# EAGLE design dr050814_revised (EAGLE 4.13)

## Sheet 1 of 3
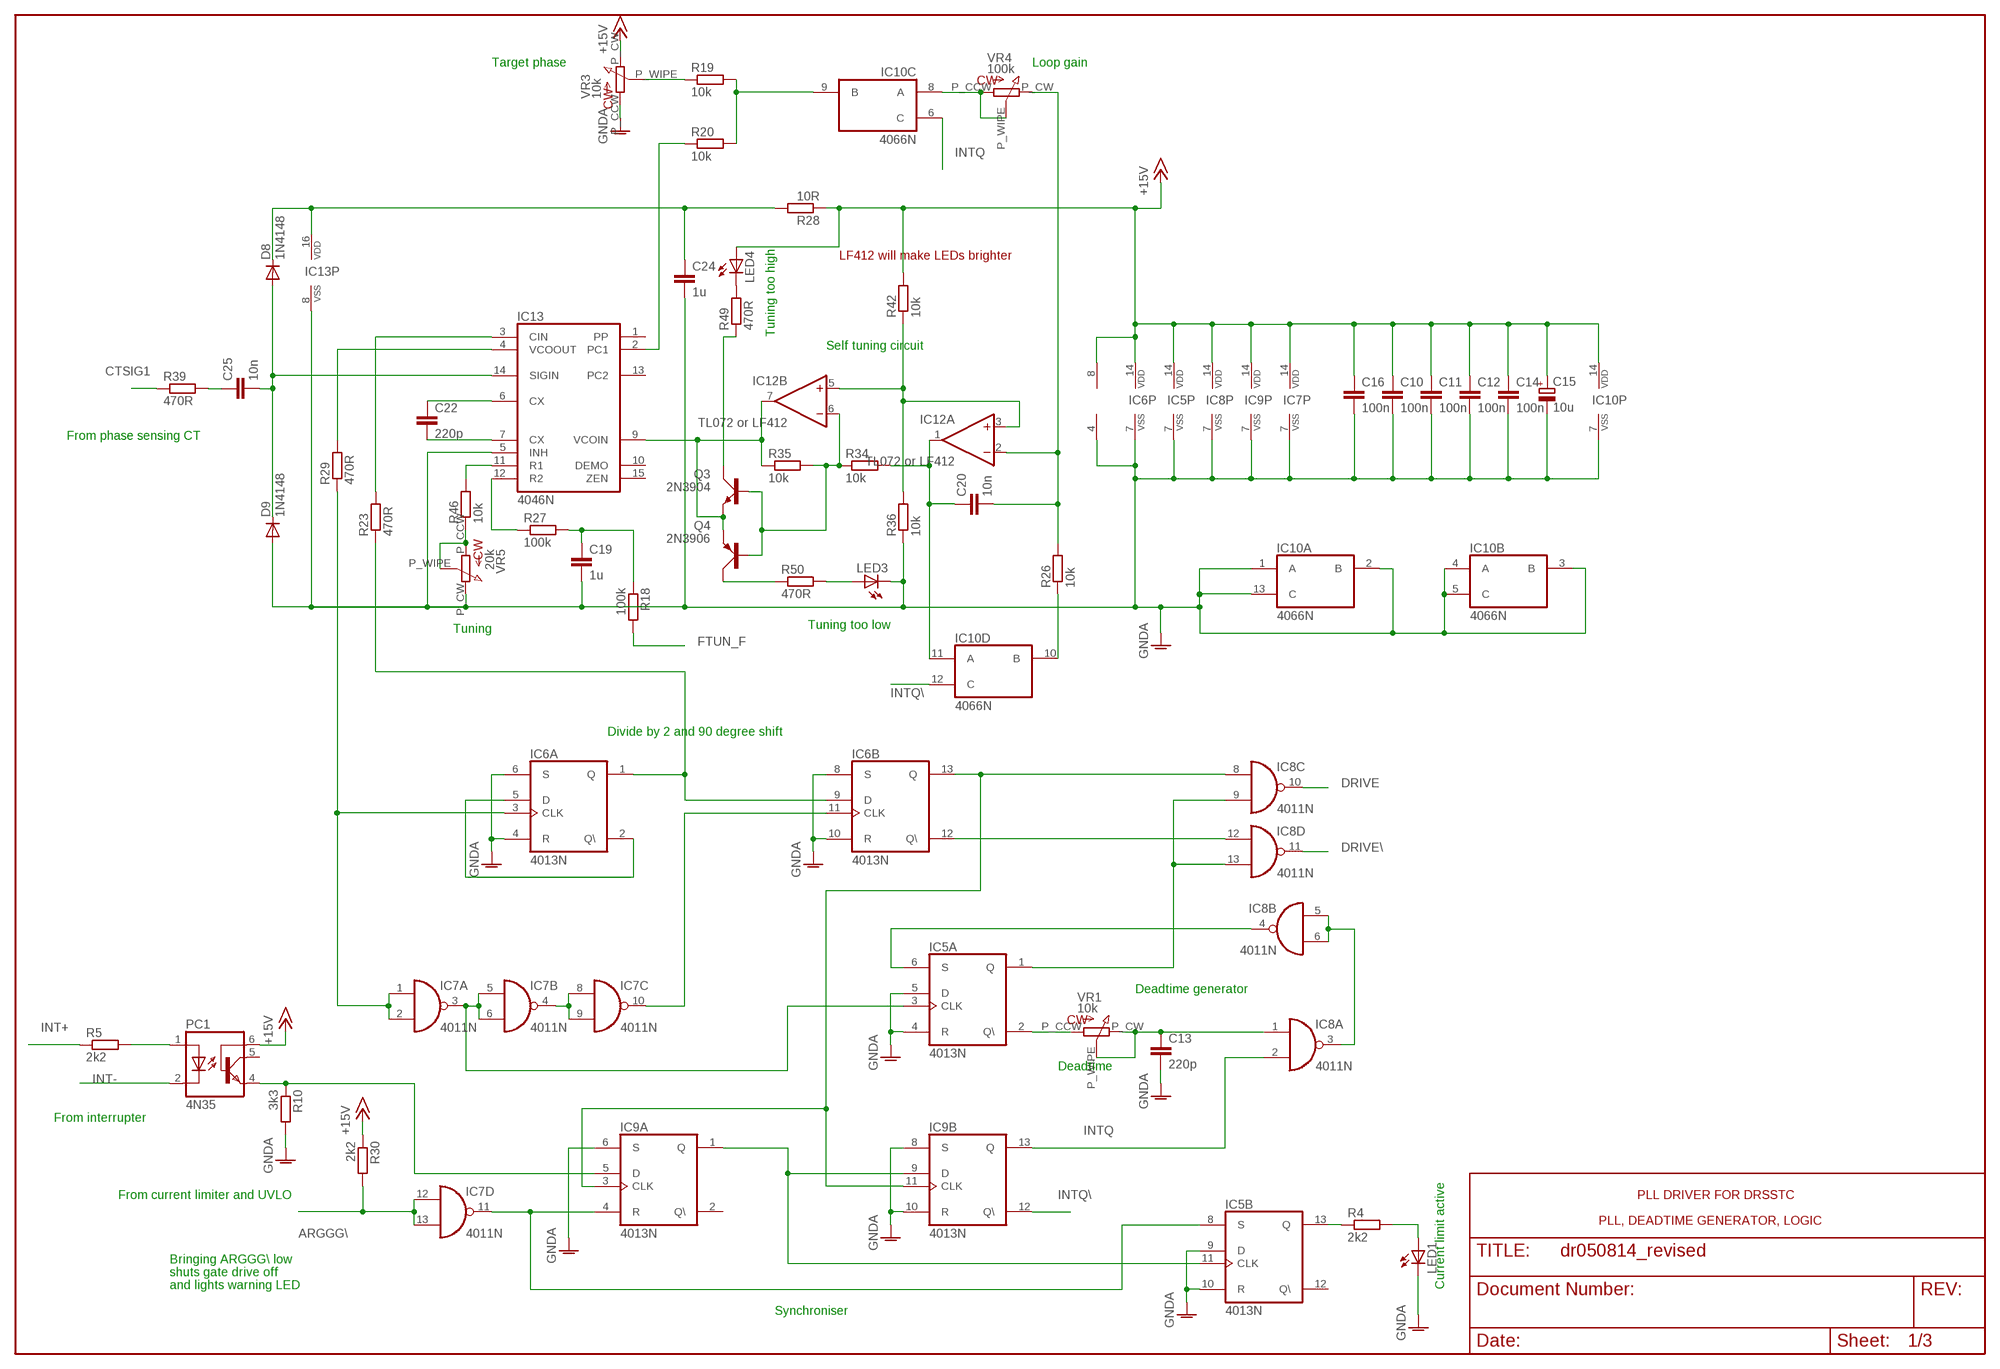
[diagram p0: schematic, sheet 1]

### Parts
C10  100n  C-EU050-025X075  [C050-025X075]
C11  100n  C-EU050-025X075  [C050-025X075]
C12  100n  C-EU050-025X075  [C050-025X075]
C13  220p  C-EU050-025X075  [C050-025X075]
C14  100n  C-EU050-025X075  [C050-025X075]
C15  10u  CPOL-EUTT6D6  [TT5D6]
C16  100n  C-EU050-025X075  [C050-025X075]
C19  1u  C-EU050-025X075  [C050-025X075]
C20  10n  C-EU050-025X075  [C050-025X075]
C22  220p  C-EU050-025X075  [C050-025X075]
C24  1u  C-EU050-025X075  [C050-025X075]
C25  10n  C-EU050-025X075  [C050-025X075]
D8  1N4148  [DO35-10]
D9  1N4148  [DO35-10]
IC5  4013N  [DIL14]
IC6  4013N  [DIL14]
IC7  4011N  [DIL14]
IC8  4011N  [DIL14]
IC9  4013N  [DIL14]
IC10  4066N  [DIL14]
IC12  TL072 or LF412  2AMP_P8+4N  [DIL08]
IC13  4046N  [DIL16]
LED1  LED5MM  [LED5MM]
LED3  LED5MM  [LED5MM]
LED4  LED5MM  [LED5MM]
PC1  4N35  [DIL06]
Q3  2N3904  [TO92D]
Q4  2N3906  [TO92D]
R4  2k2  R-EU_0207/10  [0207/10]
R5  2k2  R-EU_0207/10  [0207/10]
R10  3k3  R-EU_0207/10  [0207/10]
R18  100k  R-EU_0207/10  [0207/10]
R19  10k  R-EU_0207/10  [0207/10]
R20  10k  R-EU_0207/10  [0207/10]
R23  470R  R-EU_0207/10  [0207/10]
R26  10k  R-EU_0207/10  [0207/10]
R27  100k  R-EU_0207/10  [0207/10]
R28  10R  R-EU_0207/10  [0207/10]
R29  470R  R-EU_0207/10  [0207/10]
R30  2k2  R-EU_0207/10  [0207/10]
R34  10k  R-EU_0207/10  [0207/10]
R35  10k  R-EU_0207/10  [0207/10]
R36  10k  R-EU_0207/10  [0207/10]
R39  470R  R-EU_0207/10  [0207/10]
R42  10k  R-EU_0207/10  [0207/10]
R46  10k  R-EU_0207/10  [0207/10]
R49  470R  R-EU_0207/10  [0207/10]
R50  470R  R-EU_0207/10  [0207/10]
VR1  10k  POT  [SPECTROL149]
VR3  10k  POT  [SPECTROL149]
VR4  100k  POT  [SPECTROL149]
VR5  20k  POT  [SPECTROL149]

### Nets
+15V: C10.1 C11.1 C12.1 C14.1 C15.+ C16.1 IC5.14(P:VDD) IC6.14(P:VDD) IC7.14(P:VDD) IC8.14(P:VDD) IC9.14(P:VDD) IC10.14(P:VDD) IC12.8(P:V+) LED4.A PC1.6(BAS) R28.1 R30.1 R42.2 VR3.P_CW(CW) ; also sheet 2,3
ARGGG\: IC7.12(D:I0) IC7.13(D:I1) R30.2 ; also sheet 2
CTSIG1: R39.1 ; also sheet 3
DRIVE: IC8.10(C:O) ; also sheet 3
DRIVE\: IC8.11(D:O) ; also sheet 3
FTUN_F: R18.2 ; also sheet 3
GNDA: C10.2 C11.2 C12.2 C13.2 C14.2 C15.- C16.2 C19.2 C24.2 D9.A IC5.4(A:R) IC5.5(A:D) IC5.7(P:VSS) IC5.9(B:D) IC5.10(B:R) IC6.4(A:R) IC6.6(A:S) IC6.7(P:VSS) IC6.8(B:S) IC6.10(B:R) IC7.7(P:VSS) IC8.7(P:VSS) IC9.6(A:S) IC9.7(P:VSS) IC9.8(B:S) IC9.10(B:R) IC10.1(A:A) IC10.2(A:B) IC10.3(B:B) IC10.4(B:A) IC10.5(B:C) IC10.7(P:VSS) IC10.13(A:C) IC12.4(P:V-) IC13.5(INH) IC13.8(VSS) LED1.K(C) LED3.K(C) R10.2 R36.1 VR3.P_CCW(CCW) VR5.P_CW(CW) ; also sheet 2,3
INT+: R5.1 ; also sheet 3
INT-: PC1.2(C) ; also sheet 3
INTQ: IC8.2(A:I1) IC9.13(B:Q) IC10.6(C:C)
INTQ\: IC9.12(B:Q\) IC10.12(D:C)
N$1: C22.2 IC13.7(CX)
N$2: IC10.10(D:B) R26.1
N$3: IC12.7(B:OUT) IC13.9(VCOIN) Q3.E Q4.E R35.1
N$4: IC12.3(A:+IN) IC12.5(B:+IN) R36.2 R42.1
N$5: C24.1 D8.C IC13.16(VDD) R28.2
N$7: C22.1 IC13.6(CX)
N$8: IC6.2(A:Q\) IC6.5(A:D)
N$9: IC6.1(A:Q) IC6.9(B:D) R23.1
N$10: IC13.3(CIN) R23.2
N$11: IC13.11(R1) R46.2
N$12: IC9.5(A:D) PC1.4(EMI) R10.1
N$13: IC5.3(A:CLK) IC7.3(A:O) IC7.5(B:I0) IC7.6(B:I1)
N$14: R46.1 VR5.P_CCW(CCW) VR5.P_WIPE(WIPE)
N$16: IC7.4(B:O) IC7.8(C:I0) IC7.9(C:I1)
N$17: C20.1 IC10.11(D:A) IC12.1(A:OUT) R34.2
N$18: IC6.11(B:CLK) IC7.10(C:O)
N$19: C20.2 IC12.2(A:-IN) R26.2 VR4.P_CW(CW)
N$20: C25.2 D8.A D9.C IC13.14(SIGIN)
N$22: IC13.4(VCOOUT) R29.2
N$23: IC6.3(A:CLK) IC7.1(A:I0) IC7.2(A:I1) R29.1
N$26: PC1.1(A) R5.2
N$29: C25.1 R39.2
N$31: C13.1 IC8.1(A:I0) VR1.P_CW(CW) VR1.P_WIPE(WIPE)
N$32: IC5.1(A:Q) IC8.9(C:I1) IC8.13(D:I1)
N$33: IC6.13(B:Q) IC8.8(C:I0) IC9.3(A:CLK) IC9.11(B:CLK)
N$34: IC6.12(B:Q\) IC8.12(D:I0)
N$35: IC5.6(A:S) IC8.4(B:O)
N$36: IC8.3(A:O) IC8.5(B:I0) IC8.6(B:I1)
N$39: IC5.11(B:CLK) IC9.1(A:Q) IC9.9(B:D)
N$40: IC5.8(B:S) IC7.11(D:O) IC9.4(A:R)
N$42: IC12.6(B:-IN) Q3.B Q4.B R34.1 R35.2
N$43: LED1.A R4.2
N$44: IC5.13(B:Q) R4.1
N$47: IC10.9(C:B) R19.2 R20.2
N$48: IC13.2(PC1) R20.1
N$49: R19.1 VR3.P_WIPE(WIPE)
N$50: IC10.8(C:A) VR4.P_CCW(CCW) VR4.P_WIPE(WIPE)
N$51: Q4.C R50.1
N$52: LED3.A R50.2
N$53: LED4.K(C) R49.2
N$54: Q3.C R49.1
N$70: IC5.2(A:Q\) VR1.P_CCW(CCW)
N$71: IC13.12(R2) R27.1
N$72: C19.1 R18.1 R27.2
Unconnected: IC5.12(B:Q\) IC9.2(A:Q\) IC13.1(PP) IC13.10(DEMO) IC13.13(PC2) IC13.15(ZEN) PC1.5(COL)

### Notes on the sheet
- Target phase | Loop gain
- LF412 will make LEDs brighter
- Tuning too high
- Self tuning circuit
- From phase sensing CT
- Tuning too low
- Tuning
- Divide by 2 and 90 degree shift
- Deadtime generator
- Deadtime
- From interrupter
- From current limiter and UVLO | PLL DRIVER FOR DRSSTC
- PLL, DEADTIME GENERATOR, LOGIC
- Bringing ARGGG\ low
- shuts gate drive off
- and lights warning LED | Current limit active
- Synchroniser

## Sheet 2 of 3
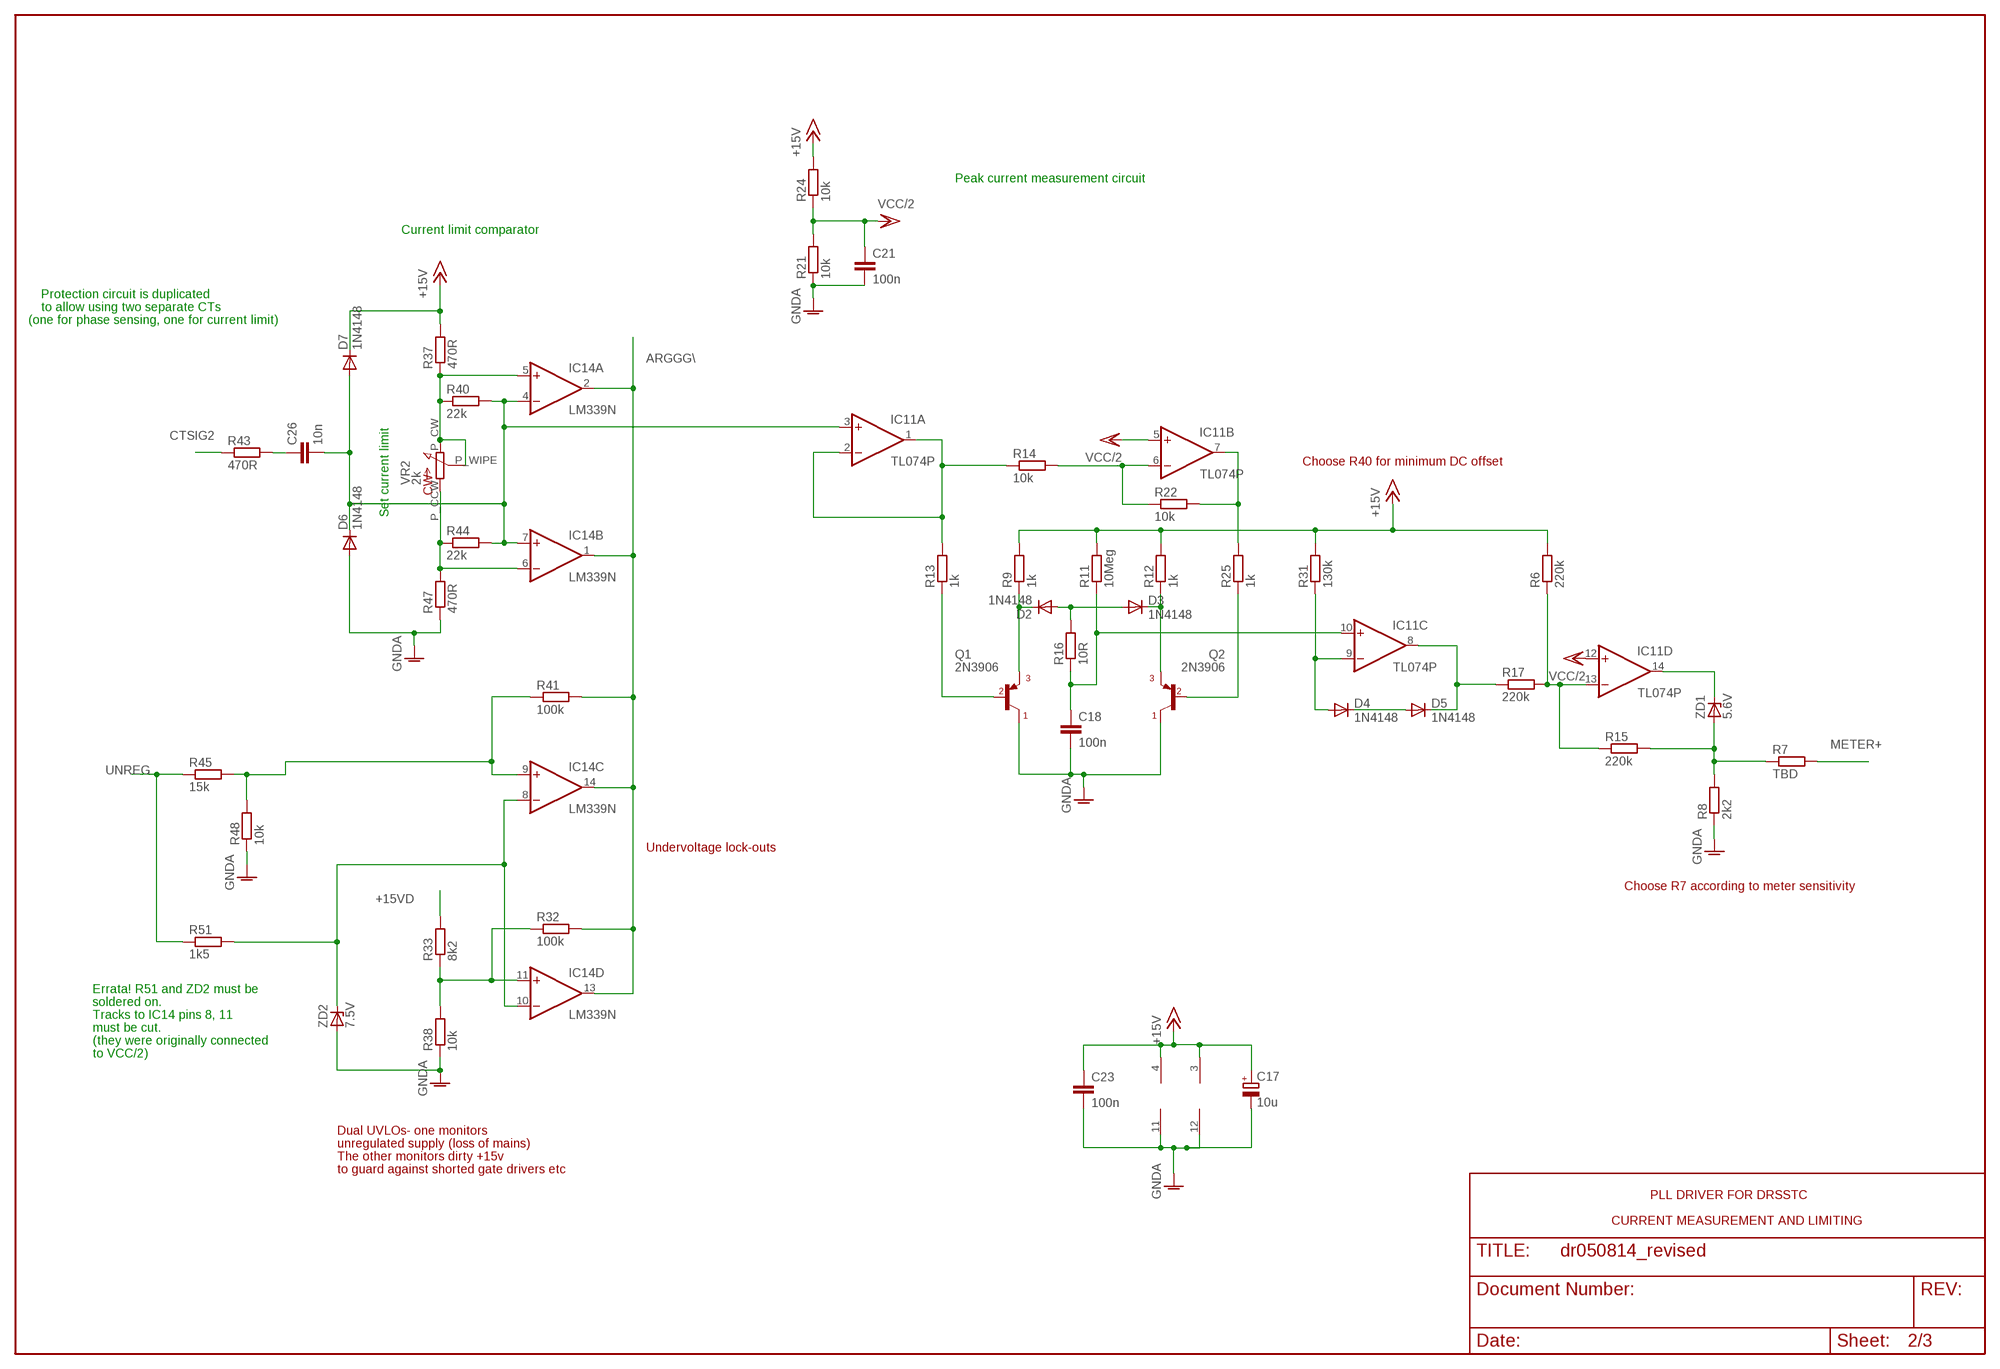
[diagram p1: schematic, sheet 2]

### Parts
C17  10u  CPOL-EUTT6D6  [TT5D6]
C18  100n  C-EU050-025X075  [C050-025X075]
C21  100n  C-EU050-025X075  [C050-025X075]
C23  100n  C-EU050-025X075  [C050-025X075]
C26  10n  C-EU050-025X075  [C050-025X075]
D2  1N4148  [DO35-10]
D3  1N4148  [DO35-10]
D4  1N4148  [DO35-10]
D5  1N4148  [DO35-10]
D6  1N4148  [DO35-10]
D7  1N4148  [DO35-10]
IC11  TL074P  [DIL14]
IC14  LM339N  [DIL14]
Q1  2N3906  [TO92]
Q2  2N3906  [TO92]
R6  220k  R-EU_0207/10  [0207/10]
R7  TBD  R-EU_0207/10  [0207/10]
R8  2k2  R-EU_0207/10  [0207/10]
R9  1k  R-EU_0207/10  [0207/10]
R11  10Meg  R-EU_0207/10  [0207/10]
R12  1k  R-EU_0207/10  [0207/10]
R13  1k  R-EU_0207/10  [0207/10]
R14  10k  R-EU_0207/10  [0207/10]
R15  220k  R-EU_0207/10  [0207/10]
R16  10R  R-EU_0207/10  [0207/10]
R17  220k  R-EU_0207/10  [0207/10]
R21  10k  R-EU_0207/10  [0207/10]
R22  10k  R-EU_0207/10  [0207/10]
R24  10k  R-EU_0207/10  [0207/10]
R25  1k  R-EU_0207/10  [0207/10]
R31  130k  R-EU_0207/10  [0207/10]
R32  100k  R-EU_0207/10  [0207/10]
R33  8k2  R-EU_0207/10  [0207/10]
R37  470R  R-EU_0207/10  [0207/10]
R38  10k  R-EU_0207/10  [0207/10]
R40  22k  R-EU_0207/10  [0207/10]
R41  100k  R-EU_0207/10  [0207/10]
R43  470R  R-EU_0207/10  [0207/10]
R44  22k  R-EU_0207/10  [0207/10]
R45  15k  R-EU_0207/10  [0207/10]
R47  470R  R-EU_0207/10  [0207/10]
R48  10k  R-EU_0207/10  [0207/10]
R51  1k5  R-EU_0207/10  [0207/10]
VR2  2k  POT  [SPECTROL149]
ZD1  5.6V  BZX55  [DO35Z10]
ZD2  7.5V  BZX55  [DO35Z10]

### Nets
+15V: C17.+ C23.1 D7.C IC11.4(P:V+) IC14.3(P:V+) R6.2 R9.2 R11.2 R12.2 R24.2 R31.2 R37.2 ; also sheet 1,3
+15VD: R33.2 ; also sheet 3
ARGGG\: IC14.1(B:OUT) IC14.2(A:OUT) IC14.13(D:OUT) IC14.14(C:OUT) R32.2 R41.2 ; also sheet 1
CTSIG2: R43.1 ; also sheet 3
GNDA: C17.- C18.2 C21.2 C23.2 D6.A IC11.11(P:V-) IC14.12(P:GND) Q1.1(C) Q2.1(C) R8.1 R21.1 R38.1 R47.1 R48.1 ZD2.A ; also sheet 1,3
METER+: R7.2 ; also sheet 3
N$24: IC14.9(C:+IN) R41.1 R45.2 R48.2
N$27: IC11.6(B:-IN) R14.2 R22.1
N$28: IC11.1(A:OUT) IC11.2(A:-IN) R13.2 R14.1
N$37: C26.1 R43.2
N$38: IC14.11(D:+IN) R32.1 R33.1 R38.2
N$41: IC11.7(B:OUT) R22.2 R25.2
N$45: C26.2 D6.C D7.A IC11.3(A:+IN) IC14.4(A:-IN) IC14.7(B:+IN) R40.2 R44.2
N$46: Q1.2(B) R13.1
N$55: IC14.6(B:-IN) R44.1 R47.2 VR2.P_CCW(CCW)
N$56: IC14.5(A:+IN) R37.1 R40.1 VR2.P_CW(CW) VR2.P_WIPE(WIPE)
N$57: Q2.2(B) R25.1
N$58: D2.C Q1.3(E) R9.1
N$59: D3.C Q2.3(E) R12.1
N$60: D2.A D3.A R16.2
N$61: C18.1 IC11.10(C:+IN) R11.1 R16.1
N$63: D5.C IC11.8(C:OUT) R17.1
N$64: D4.C D5.A
N$65: D4.A IC11.9(C:-IN) R31.1
N$66: IC11.13(D:-IN) R6.1 R15.1 R17.2
N$67: IC11.14(D:OUT) ZD1.C
N$68: R7.1 R8.2 R15.2 ZD1.A
N$75: IC14.8(C:-IN) IC14.10(D:-IN) R51.2 ZD2.C
UNREG: R45.1 R51.1 ; also sheet 3
VCC/2: C21.1 IC11.5(B:+IN) IC11.12(D:+IN) R21.2 R24.1

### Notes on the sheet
- Peak current measurement circuit
- Current limit comparator
- Protection circuit is duplicated
- to allow using two separate CTs
- (one for phase sensing, one for current limit)
- Choose R40 for minimum DC offset
- Set current limit
- Undervoltage lock-outs
- Choose R7 according to meter sensitivity
- Errata! R51 and ZD2 must be
- soldered on.
- Tracks to IC14 pins 8, 11
- must be cut.
- (they were originally connected
- to VCC/2)
- Dual UVLOs- one monitors
- unregulated supply (loss of mains)
- The other monitors dirty +15v
- to guard against shorted gate drivers etc
- PLL DRIVER FOR DRSSTC
- CURRENT MEASUREMENT AND LIMITING

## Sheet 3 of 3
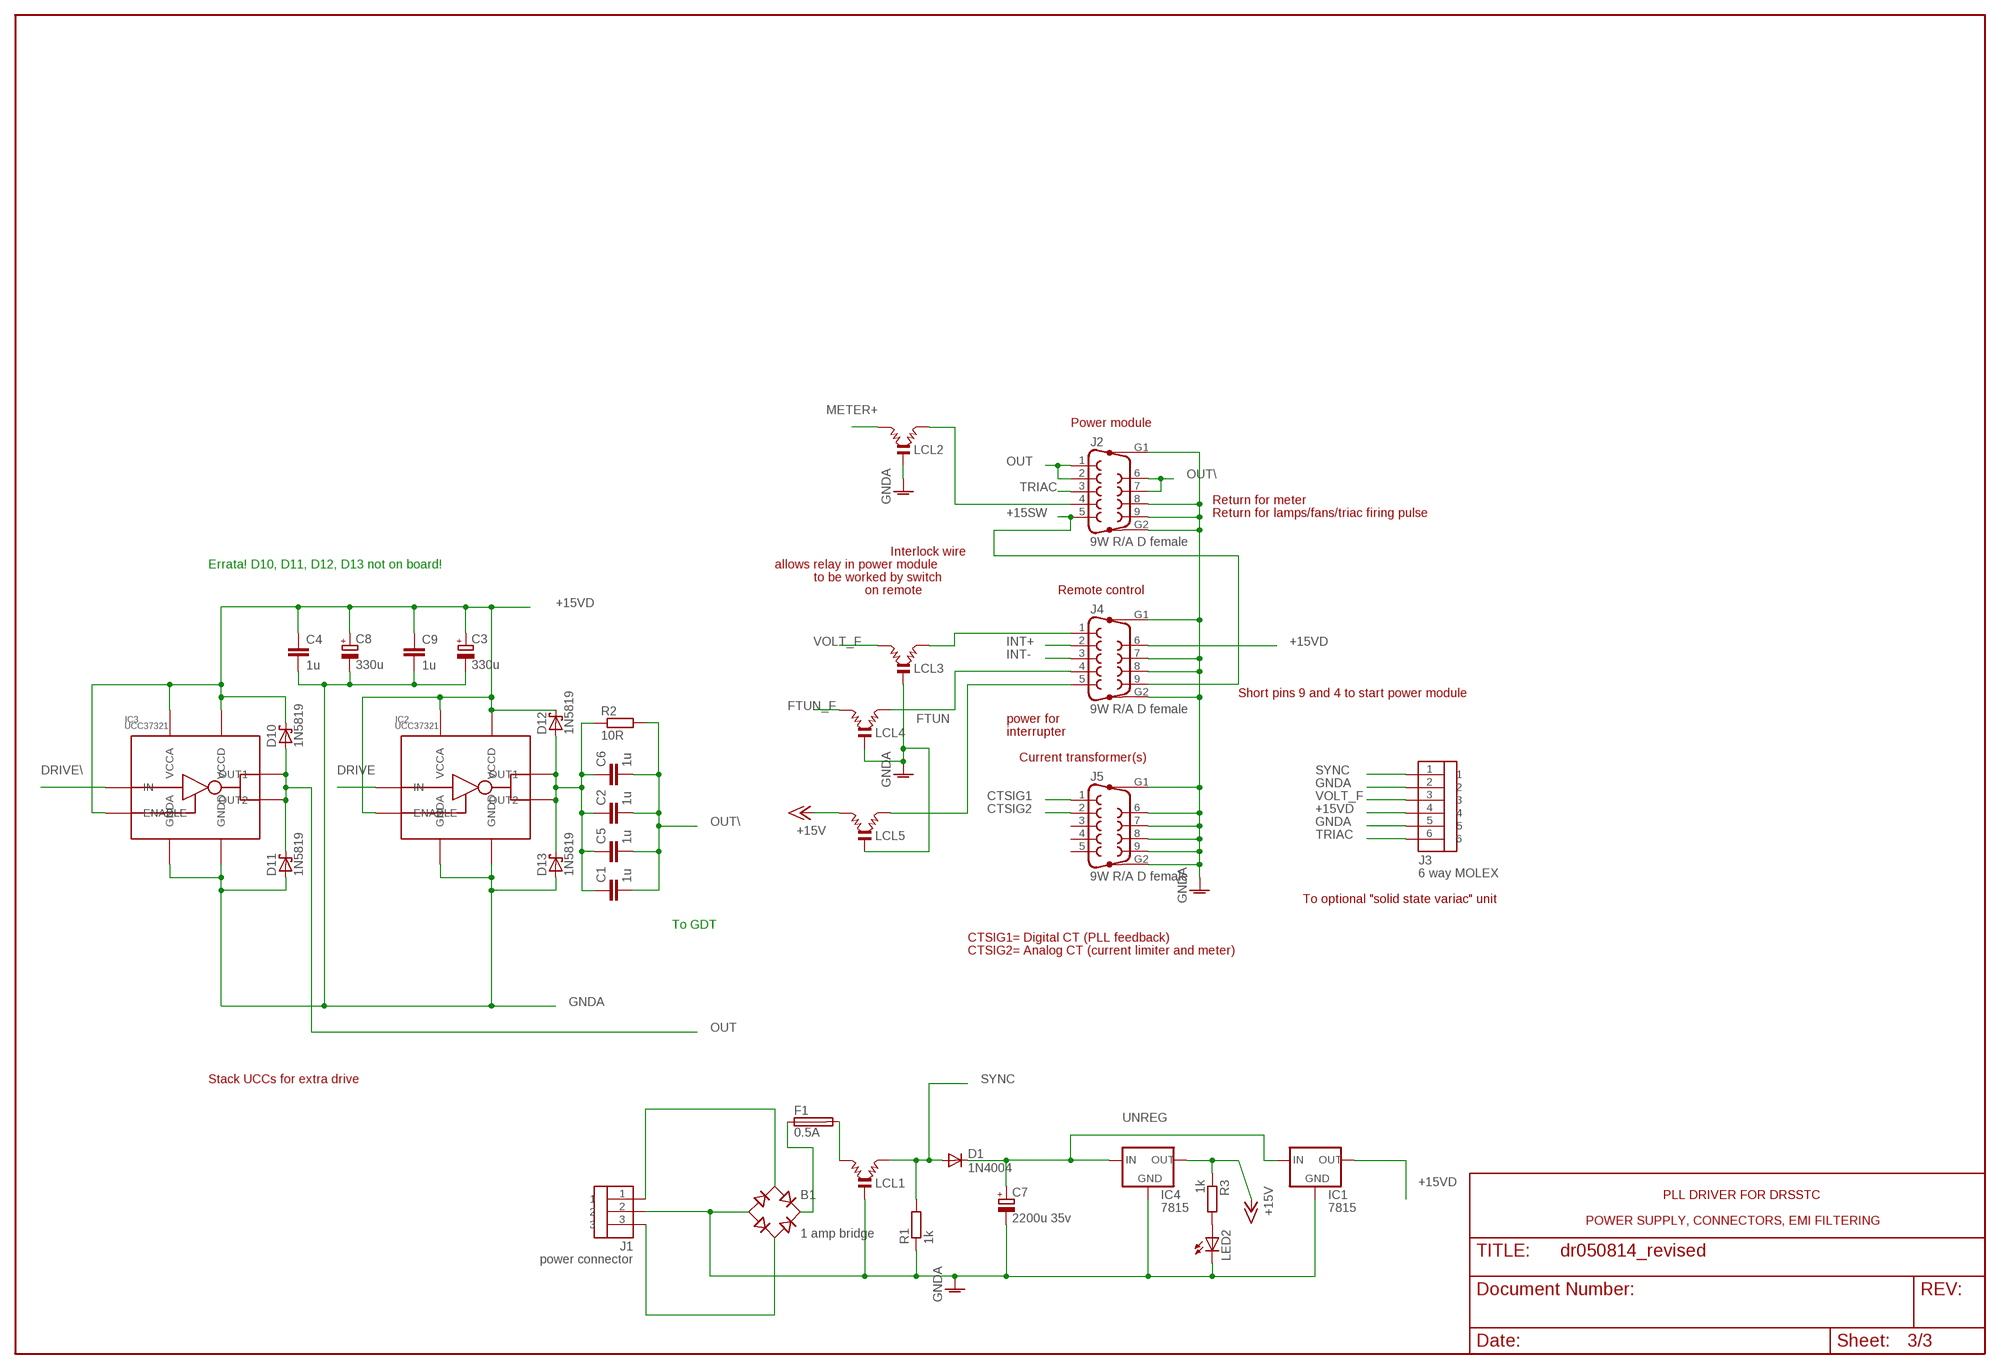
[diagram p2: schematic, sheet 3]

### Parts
B1  1 amp bridge  RB1A  [RB1A]
C1  1u  C-EU025-040X050  [C025-040X050]
C2  1u  C-EU025-040X050  [C025-040X050]
C3  330u  CPOL-EUE3.5-10  [E3,5-10]
C4  1u  C-EU050-025X075  [C050-025X075]
C5  1u  C-EU025-040X050  [C025-040X050]
C6  1u  C-EU025-040X050  [C025-040X050]
C7  2200u 35v  CPOL-EUE7.5-18  [E7,5-18]
C8  330u  CPOL-EUE3.5-10  [E3,5-10]
C9  1u  C-EU050-025X075  [C050-025X075]
D1  1N4004  [DO41-10]
D10  1N5819  SCHOTTKY-DIODEF126Z12  [F126Z12]
D11  1N5819  SCHOTTKY-DIODEF126Z12  [F126Z12]
D12  1N5819  SCHOTTKY-DIODEF126Z12  [F126Z12]
D13  1N5819  SCHOTTKY-DIODEF126Z12  [F126Z12]
F1  0.5A  SH22,5  [SH22,5]
IC1  7815  78XXS  [78XXS]
IC2  UCC37321  [DIL08]
IC3  UCC37321  [DIL08]
IC4  7815  78XXS  [78XXS]
J1  power connector  P3-5  [P3-5]
J2  9W R/A D female  F09HP  [F09HP]
J3  6 way MOLEX  6MOLEX  [6MOLEX]
J4  9W R/A D female  F09HP  [F09HP]
J5  9W R/A D female  F09HP  [F09HP]
LCL1  LCL  [LCL]
LCL2  LCL  [LCL]
LCL3  LCL  [LCL]
LCL4  LCL  [LCL]
LCL5  LCL  [LCL]
LED2  LED5MM  [LED5MM]
R1  1k  R-EU_0207/10  [0207/10]
R2  10R  R-EU_0207/10  [0207/10]
R3  1k  R-EU_0207/10  [0207/10]

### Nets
+15SW: J2.5 J4.9
+15V: IC4.OUT LCL5.1 R3.1 ; also sheet 1,2
+15VD: C3.+ C4.1 C8.+ C9.1 D10.C D12.C IC1.OUT IC2.1(VCCA) IC2.3(ENABLE) IC2.8(VCCD) IC3.1(VCCA) IC3.3(ENABLE) IC3.8(VCCD) J3.4 J4.6 ; also sheet 2
CTSIG1: J5.1 ; also sheet 1
CTSIG2: J5.2 ; also sheet 2
DRIVE: IC2.2(IN) ; also sheet 1
DRIVE\: IC3.2(IN) ; also sheet 1
FTUN: J4.4 LCL4.2
FTUN_F: LCL4.1 ; also sheet 1
GNDA: B1.- C3.- C4.2 C7.- C8.- C9.2 D11.A D13.A IC1.GND IC2.4(GNDA) IC2.5(GNDD) IC3.4(GNDA) IC3.5(GNDD) IC4.GND J1.2 J2.8 J2.9 J2.G1 J2.G2 J3.2 J3.5 J4.7 J4.8 J4.G1 J4.G2 J5.6 J5.7 J5.8 J5.9 J5.G1 J5.G2 LCL1.0(GND) LCL2.0(GND) LCL3.0(GND) LCL4.0(GND) LCL5.0(GND) LED2.K(C) R1.1 ; also sheet 1,2
INT+: J4.2 ; also sheet 1
INT-: J4.3 ; also sheet 1
METER+: LCL2.1 ; also sheet 2
N$6: J4.1 LCL3.2
N$15: J2.4 LCL2.2
N$21: B1.+ F1.1
N$25: B1.AC1 J1.1
N$30: J4.5 LCL5.2
N$62: B1.AC2 J1.3
N$69: LED2.A R3.2
N$73: C1.1 C2.1 C5.1 C6.1 D12.A D13.C IC2.6(OUT2) IC2.7(OUT1) R2.1
N$74: F1.2 LCL1.1
OUT: D10.A D11.C IC3.6(OUT2) IC3.7(OUT1) J2.1 J2.2
OUT\: C1.2 C2.2 C5.2 C6.2 J2.6 J2.7 R2.2
SYNC: D1.A J3.1 LCL1.2 R1.2
TRIAC: J2.3 J3.6
UNREG: C7.+ D1.C IC1.IN IC4.IN ; also sheet 2
VOLT_F: J3.3 LCL3.1
Unconnected: J5.3 J5.4 J5.5

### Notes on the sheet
- Power module
- Return for meter
- Return for lamps/fans/triac firing pulse
- Interlock wire
- Errata! D10, D11, D12, D13 not on board! | allows relay in power module
- to be worked by switch
- on remote | Remote control
- Short pins 9 and 4 to start power module
- power for
- interrupter
- Current transformer(s)
- To optional "solid state variac" unit
- To GDT
- CTSIG1= Digital CT (PLL feedback)
- CTSIG2= Analog CT (current limiter and meter)
- Stack UCCs for extra drive
- PLL DRIVER FOR DRSSTC
- POWER SUPPLY, CONNECTORS, EMI FILTERING

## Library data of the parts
B1 = rectifier:RB1A: RECTIFIER 1 A
C1 C2 C4-C6 C9-C14 C16 C18 C19 C21-C26 = rcl:C-EU: CAPACITOR, European symbol
C3 C7 C8 C15 C17 = rcl:CPOL-EU: POLARIZED CAPACITOR, European symbol
C20 = rcl_dm:C-EU: CAPACITOR, European symbol
D1 = diode:1N4004: DIODE
D2-D9 = diode:1N4148: DIODE
D10-D13 = diode:SCHOTTKY-DIODE: Schottky Diode
F1 = fuse:SH22,5: FUSE HOLDER
IC1 IC4 = v-reg:78XXS: VOLTAGE REGULATOR
IC2 IC3 = tesla:UCC37321
IC5 IC6 IC9 = 40xx:4013: Dual D FLIP FLOP, set/reset
IC7 IC8 = 40xx:4011: Quad 2-input NAND
IC10 = 40xx:4066: Quad bilateral ANALOG SWITCH
IC11 = linear_optosci:TL074: OP AMP
IC12 = linear:2AMP_P8+4: OP AMP
IC13 = 40xx:4046: Micropower PLL
IC14 = linear_optosci:LM339: Low Power Low Offset Voltage Quad Comparators with open collector; LM139/LM239/LM339/LM2901/LM3302
J1 = CONNDM:P3-5
J2 J4 J5 = con-subd:F09HP: SUB-D
J3 = CONNDM:6MOLEX
LCL1-LCL5 = murata-filter:LCL: FILTER
LED1-LED4 = led:LED: LED
PC1 = optocoupler:4N35: MOTOROLA OPTO COUPLER
Q1 Q2 = transistors_optosci:2N3906: PNP Transistor
Q3 = transistor-small-signal:2N3904: NPN TRANSISTOR
Q4 = transistor-small-signal:2N3906: PNP TRANSISTOR
R1-R51 = rcl:R-EU_: RESISTOR, European symbol
VR1-VR5 = tesla:POT
ZD1 ZD2 = diode:BZX55: Z DIODE

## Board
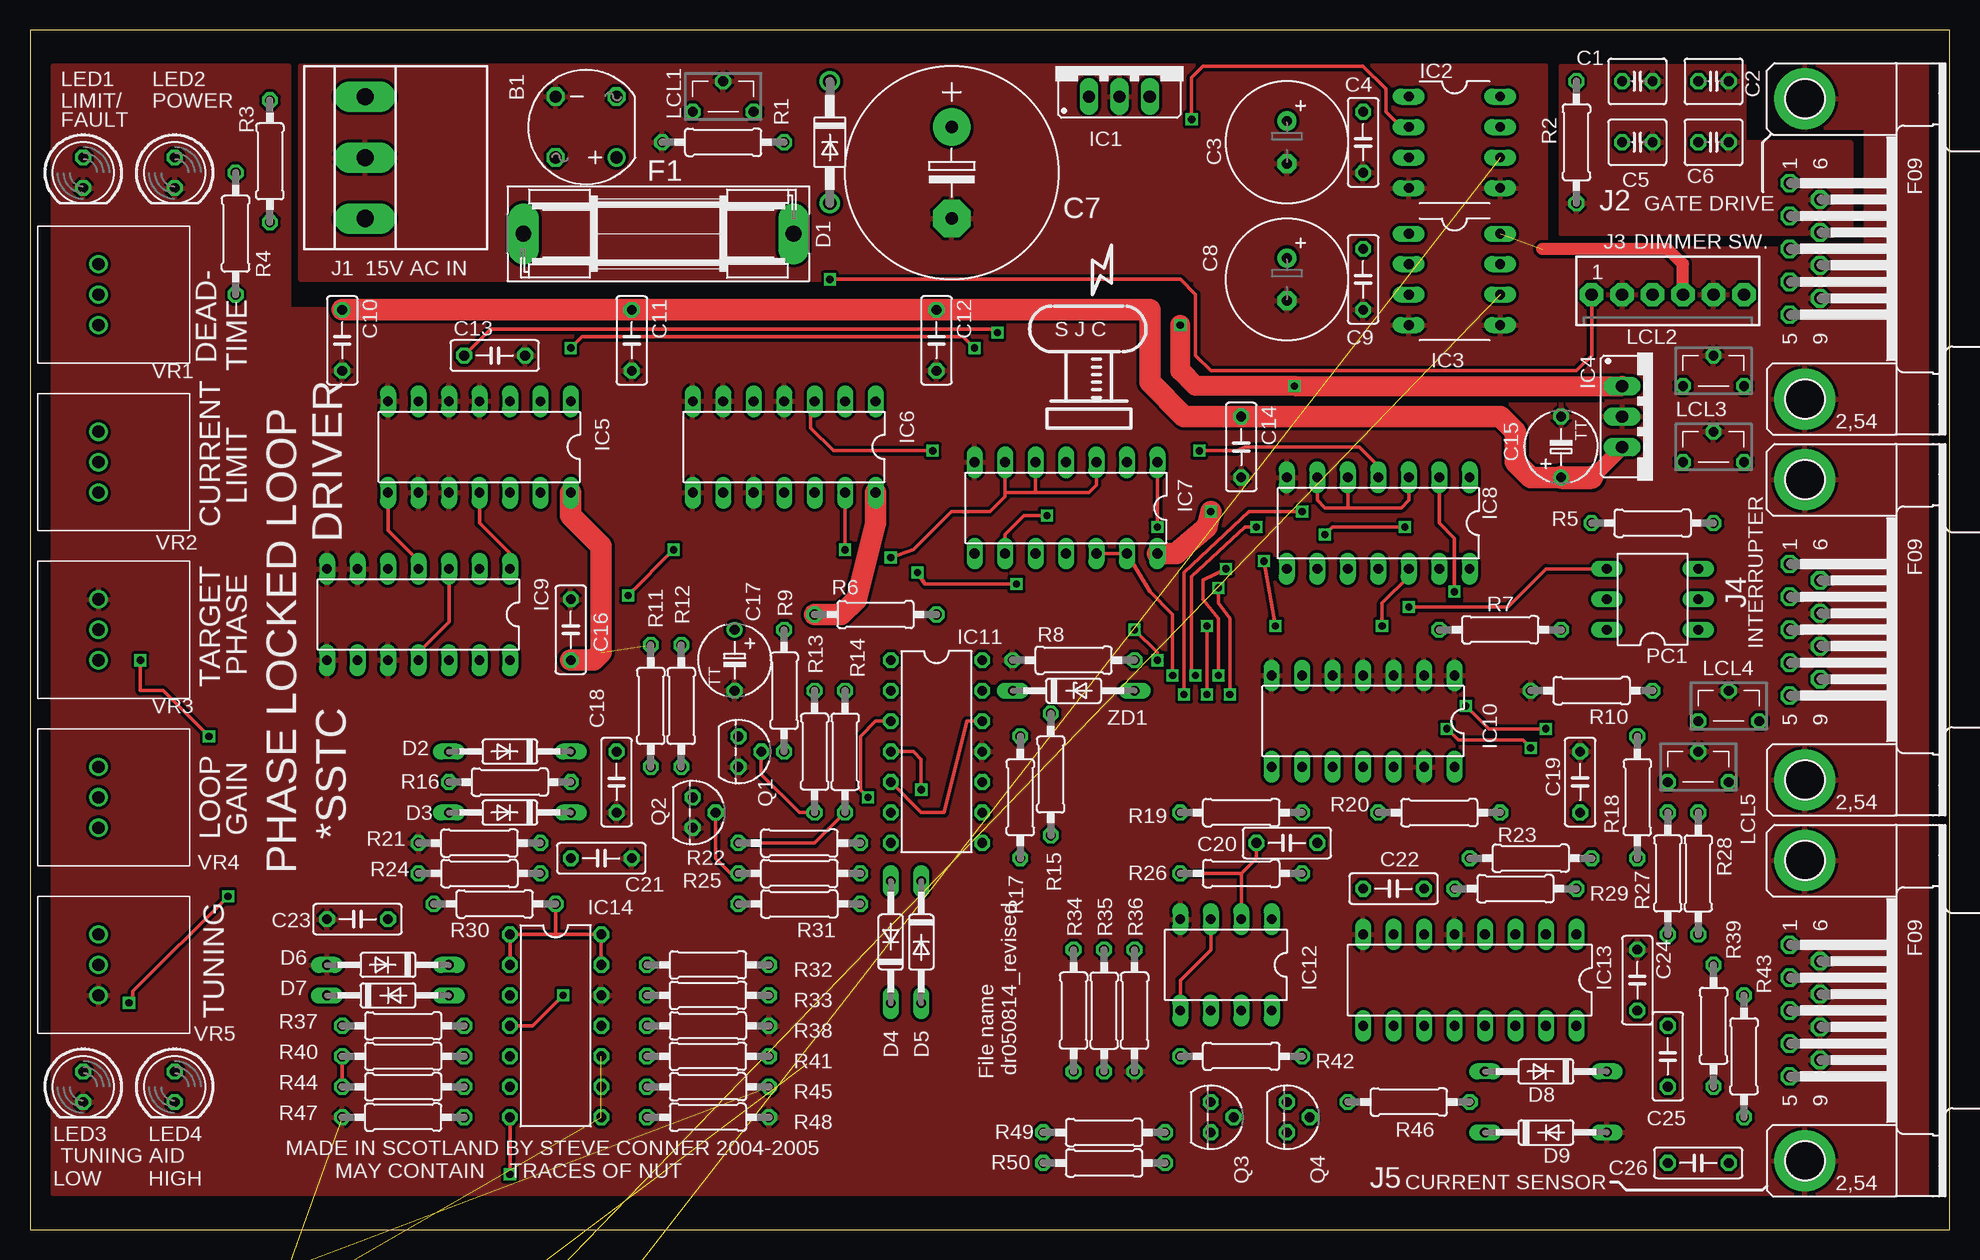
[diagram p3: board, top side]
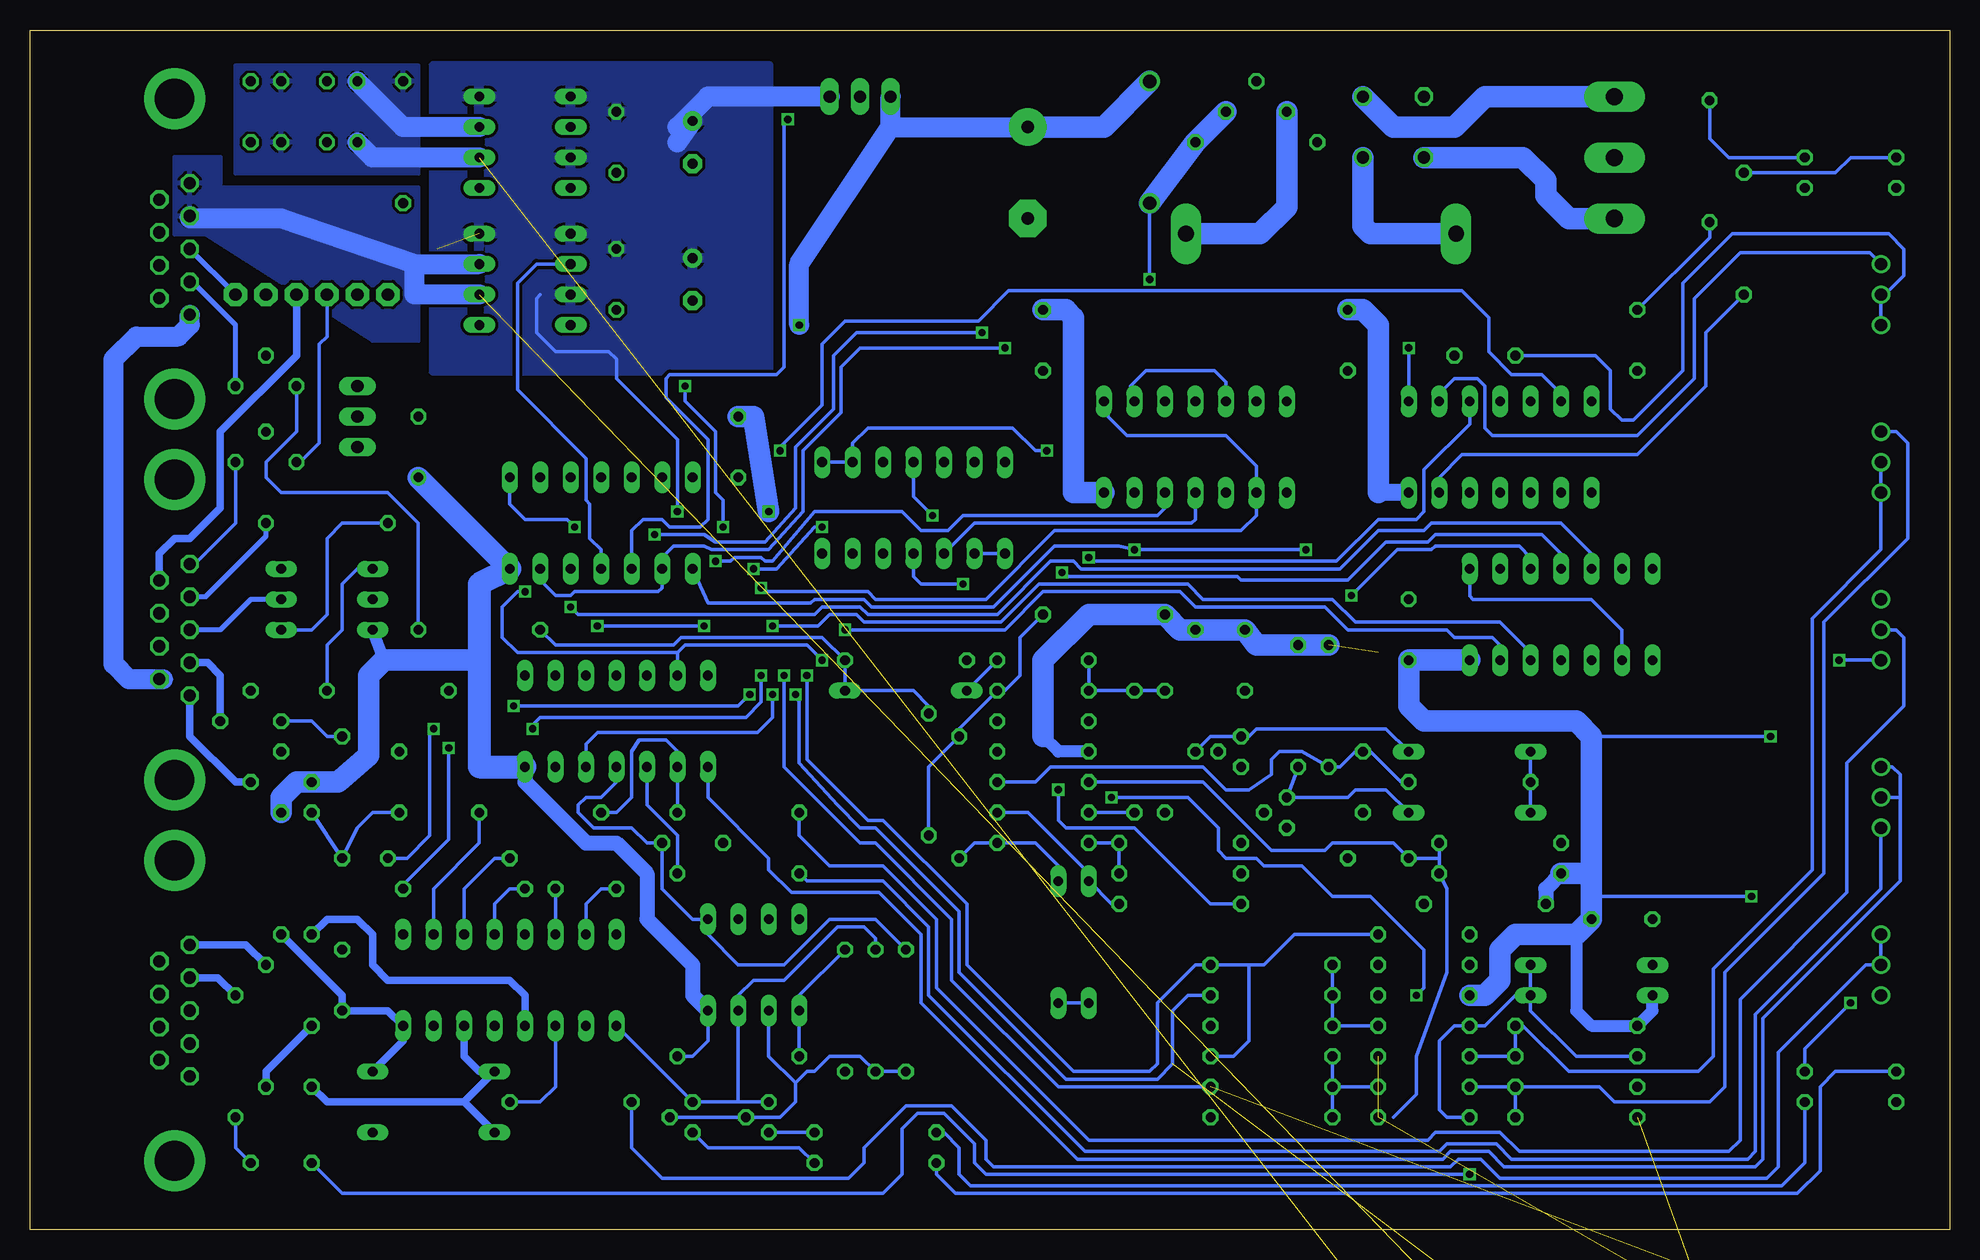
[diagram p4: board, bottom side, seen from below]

Size 160 x 100 mm. Coordinates in mm from the lower left corner, seen from the top.
Outline: 0,0 160,0 160,100 0,100 0,0
Copper layers (1*16): Top 0.035mm / dielectric 1.5mm / Bottom 0.035mm
Design rules "10mil": minimum track width 10mil, minimum drill 23mil, track to track 10mil, track to pad 10mil, pad to pad 10mil, via to via 10mil, smd to smd 8mil, copper to edge 40mil, drill to drill 8mil, minimum pad ring 10mil, minimum via ring 8mil, stop-mask expansion 4mil, vias tented up to drill 0mil, thermal gap 10mil

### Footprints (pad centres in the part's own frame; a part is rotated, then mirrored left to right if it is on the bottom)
RB1A = drill 1.016 round: + -2.54,2.54 | drill 1.016 octagon: - 2.54,-2.54; AC1 2.54,2.54; AC2 -2.54,-2.54
C025-040X050 = drill 0.813 octagon: 1 -1.27,0; 2 1.27,0
E3,5-10 = drill 0.813 pad 1.6 round: + -1.778,0 | drill 0.813 pad 1.6 octagon: - 1.778,0
C050-025X075 = drill 0.813 octagon: 1 -2.54,0; 2 2.54,0
E7,5-18 = drill 1.016 pad 3.15 round: + -3.81,0 | drill 1.016 pad 3.15 octagon: - 3.81,0
TT5D6 = drill 0.813 round: + -2.54,0 | drill 0.813 octagon: - 2.54,0
DO41-10 = drill 1.118 round: A 5.08,0; C -5.08,0
DO35-10 = drill 0.813 long: A 5.08,0; C -5.08,0
F126Z12 = drill 1.016 long: A 6.35,0; C -6.35,0
SH22,5 = drill 1.321 pad 2.54 long: 1 -11.252,0; 2 11.252,0
78XXS = drill 1.016 long: GND 0,-2.54; IN -2.54,-2.54; OUT 2.54,-2.54
DIL08 = drill 0.813 long: 1 -3.81,-3.81; 2 -1.27,-3.81; 3 1.27,-3.81; 4 3.81,-3.81; 5 3.81,3.81; 6 1.27,3.81; 7 -1.27,3.81; 8 -3.81,3.81
DIL14 = drill 0.813 long: 1 -7.62,-3.81; 2 -5.08,-3.81; 3 -2.54,-3.81; 4 0,-3.81; 5 2.54,-3.81; 6 5.08,-3.81; 7 7.62,-3.81; 8 7.62,3.81; 9 5.08,3.81; 10 2.54,3.81; 11 0,3.81; 12 -2.54,3.81; 13 -5.08,3.81; 14 -7.62,3.81
DIL14' = drill 0.813 octagon: 1 -7.62,-3.81; 2 -5.08,-3.81; 3 -2.54,-3.81; 4 0,-3.81; 5 2.54,-3.81; 6 5.08,-3.81; 7 7.62,-3.81; 8 7.62,3.81; 9 5.08,3.81; 10 2.54,3.81; 11 0,3.81; 12 -2.54,3.81; 13 -5.08,3.81; 14 -7.62,3.81
DIL16 = drill 0.813 long: 1 -8.89,-3.81; 2 -6.35,-3.81; 3 -3.81,-3.81; 4 -1.27,-3.81; 5 1.27,-3.81; 6 3.81,-3.81; 7 6.35,-3.81; 8 8.89,-3.81; 9 8.89,3.81; 10 6.35,3.81; 11 3.81,3.81; 12 1.27,3.81; 13 -1.27,3.81; 14 -3.81,3.81; 15 -6.35,3.81; 16 -8.89,3.81
P3-5 = drill 1.422 pad 2.54 long: 1 0,5.08; 2 0,0; 3 0,-5.08
F09HP = drill 1.016 octagon: 1 -5.486,-1.27; 2 -2.743,-1.27; 3 0,-1.27; 4 2.743,-1.27; 5 5.486,-1.27; 6 -4.115,1.27; 7 -1.372,1.27; 8 1.372,1.27; 9 4.115,1.27 | drill 3.302 pad 5.08 round: G1 -12.522,0; G2 12.522,0
6MOLEX = drill 1.016 pad 1.93 octagon: 1 -6.35,0; 2 -3.81,0; 3 -1.27,0; 4 1.27,0; 5 3.81,0; 6 6.35,0
LCL = drill 0.813 octagon: 0 0,1.27; 1 -2.54,-1.27; 2 2.54,-1.27
LED5MM = drill 0.813 octagon: A -1.27,0; K 1.27,0
DIL06 = drill 0.813 long: 1 -2.54,-3.81; 2 0,-3.81; 3 2.54,-3.81; 4 2.54,3.81; 5 0,3.81; 6 -2.54,3.81
TO92 = drill 0.813 octagon: 1 1.27,0; 2 0,1.905; 3 -1.27,0
TO92D = drill 0.813 octagon: B 0,1.905; C 1.27,0; E -1.27,0
0207/10 = drill 0.813 octagon: 1 -5.08,0; 2 5.08,0
SPECTROL149 = drill 1.016 round: P_CCW -2.54,5.08; P_CW 2.54,5.08; P_WIPE 0,5.08
DO35Z10 = drill 0.813 long: A 5.08,0; C -5.08,0

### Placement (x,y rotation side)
B1  46.35,91.91 180 top
C1  133.98,95.72 0 top
C2  140.33,95.72 0 top
C3  104.77,90.64 270 top
C4  111.12,90.64 270 top
C5  133.98,90.64 0 top
C6  140.33,90.64 0 top
C7  76.83,88.1 270 top
C8  104.77,79.21 270 top
C9  111.12,79.21 270 top
C10  26.03,74.13 270 top
C11  50.16,74.13 270 top
C12  75.56,74.13 270 top
C13  38.73,72.86 0 top
C14  100.96,65.24 270 top
C15  127.63,65.24 90 top
C16  45.08,50 90 top
C17  58.73,47.46 270 top
C18  48.89,37.3 270 top
C19  129.22,37.3 90 top
C20  104.77,32.22 180 top
C21  47.62,30.95 0 top
C22  113.66,28.41 180 top
C23  27.3,25.87 180 top
C24  133.98,20.79 90 top
C25  136.52,14.44 270 top
C26  139.06,5.55 180 top
D1  66.67,90.64 270 top
D2  40,39.84 180 top
D3  40,34.76 180 top
D4  71.75,23.96 90 top
D5  74.29,23.96 270 top
D6  29.84,22.06 180 top
D7  29.84,19.52 0 top
D8  126.36,13.17 180 top
D9  126.36,8.09 0 top
D10  not placed on the board
D11  not placed on the board
D12  not placed on the board
D13  not placed on the board
F1  52.38,83.02 0 top
IC1  90.8,96.99 0 top
IC2  118.74,90.64 270 top
IC3  118.74,79.21 270 top
IC4  135.25,67.78 270 top
IC5  37.46,65.24 180 top
IC6  62.86,65.24 180 top
IC7  86.35,60.16 180 top
IC8  112.39,58.89 180 top
IC9  32.38,51.27 180 top
IC10  111.12,42.38 180 top
IC11  TL074P  [DIL14']  75.56,39.84 270 top
IC12  99.69,22.06 180 top
IC13  120.01,20.79 180 top
IC14  LM339N  [DIL14']  43.81,16.98 270 top
J1  27.93,89.37 180 top
J2  147.95,81.75 270 top
J3  136.52,77.94 0 top
J4  147.95,50 270 top
J5  147.95,18.25 270 top
LCL1  57.78,94.45 0 top
LCL2  140.33,71.59 0 top
LCL3  140.33,65.24 0 top
LCL4  141.6,43.65 0 top
LCL5  139.06,38.57 0 top
LED1  4.44,88.1 270 top
LED2  12.06,88.1 270 top
LED3  4.44,11.9 270 top
LED4  12.06,11.9 270 top
PC1  135.25,52.54 90 top
Q1  59.05,39.84 270 top
Q2  55.24,34.76 270 top
Q3  98.42,9.36 270 top
Q4  104.77,9.36 270 top
R1  57.78,90.64 0 top
R2  128.9,90.64 270 top
R3  20,89.05 90 top
R4  17.14,83.02 90 top
R5  135.25,58.89 180 top
R6  70.48,51.27 180 top
R7  122.55,50 0 top
R8  86.99,47.46 0 top
R9  62.86,44.92 90 top
R10  130.17,44.92 180 top
R11  51.75,43.65 90 top
R12  54.29,43.65 90 top
R13  65.4,39.84 90 top
R14  67.94,39.84 270 top
R15  85.08,37.94 90 top
R16  40,37.3 180 top
R17  82.55,36.03 90 top
R18  133.98,36.03 90 top
R19  100.96,34.76 0 top
R20  117.47,34.76 180 top
R21  37.46,32.22 0 top
R22  64.13,32.22 0 top
R23  125.09,30.95 180 top
R24  37.46,29.68 180 top
R25  64.13,29.68 0 top
R26  100.96,29.68 180 top
R27  136.52,29.68 90 top
R28  139.06,29.68 270 top
R29  123.82,28.41 180 top
R30  38.73,27.14 0 top
R31  64.13,27.14 180 top
R32  56.51,22.06 0 top
R33  56.51,19.52 0 top
R34  86.99,18.25 90 top
R35  89.53,18.25 270 top
R36  92.07,18.25 90 top
R37  31.11,16.98 180 top
R38  56.51,16.98 180 top
R39  140.33,16.98 270 top
R40  31.11,14.44 180 top
R41  56.51,14.44 0 top
R42  100.96,14.44 0 top
R43  142.87,14.44 270 top
R44  31.11,11.9 180 top
R45  56.51,11.9 180 top
R46  114.93,10.63 0 top
R47  31.11,9.36 0 top
R48  56.51,9.36 180 top
R49  89.53,8.09 180 top
R50  89.53,5.55 180 top
R51  not placed on the board
VR1  0.63,77.94 270 top
VR2  0.63,63.97 270 top
VR3  0.63,50 270 top
VR4  0.63,36.03 270 top
VR5  0.63,22.06 270 top
ZD1  86.99,44.92 0 top
ZD2  not placed on the board

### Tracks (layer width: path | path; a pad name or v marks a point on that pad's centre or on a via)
+15SW
  Bottom 1.676: J2.5 146.68,75.4 147.63,74.45 151.12,74.45 153.03,72.54 153.03,47.14 151.76,45.87 148.9,45.87 148.91,45.88 J4.9
+15V  (via drill 0.6)  (1 unrouted)
  Top 0.305: IC11.4 73.66,39.84 74.29,39.2 v74.29,36.66 | v14.92,41.11 11.11,44.92 9.2,44.92 v9.2,47.46 | v16.5,27.77 8.57,19.84 8.57,19.2 v8.25,18.88
  Top 1.27: 130.17,62.7 IC4.OUT
  Top 1.778: C15.+ 125.09,62.7 123.82,63.97 123.82,66.51 122.55,67.78 C14.1 96.2,67.78 93.34,70.64 93.34,76.67 C12.1 C10.1 | v98.42,59.84 98.1,58.57 95.88,56.67 95.56,56.35 IC7.14 | R6.2 67.62,51.27 68.89,52.54 70.48,58.89 IC6.14 | C16.1 46.98,47.46 47.62,48.09 47.62,56.98 45.08,59.52 IC5.14
  Top 1.93: C15.+ 130.17,62.7
  Bottom 0.305: IC12.8 103.5,15.71 104.77,14.44 R42.2 | v74.29,36.66 74.29,34.12 73.66,33.49 67.94,33.49 61.59,27.14 R31.2 | C10.1 20,82.7 R3.1 | v9.2,47.46 VR3.P_CW | 29.84,41.11 v14.92,41.11 | LED4.A 12.06,15.08 v8.25,18.88 | 30.16,27.77 29.84,27.77 v16.5,27.77
  Bottom 1.016: 31.11,24.6 31.11,18.25 29.84,16.98 R37.2 24.76,18.25 D7.C | IC11.4 74.29,39.84 75.56,41.11 | 130.49,47.46 PC1.6
  Bottom 1.27: IC10.14 118.74,37.3 113.66,32.22 111.12,32.22 108.58,29.68 108.58,25.87 104.77,22.06 104.77,19.52 IC12.8 | R30.1 33.65,28.41 R24.2
  Bottom 1.422: IC5.14 47.62,61.43
  Bottom 1.778: C14.1 99.69,67.78 v98.42,59.84 | C15.+ IC8.14 | IC6.14 73.02,61.43 73.02,76.03 73.66,76.67 C12.1 | C11.1 48.89,76.67 47.62,75.4 47.62,61.43 | IC9.14 C16.1 45.08,43.65 43.81,42.38 31.11,42.38 29.84,41.11 29.84,29.68 | IC14.3 38.73,19.52 37.46,20.79 37.46,23.33 36.19,24.6 31.11,24.6 C23.1 29.84,27.77 29.84,29.68 | 29.84,29.68 R24.2 | R11.2 R12.2 57.78,48.73 C17.+ R9.2 64.13,50 R6.2 71.75,51.27 75.56,47.46 75.56,41.11 | R28.1 139.06,36.03 137.79,37.3 LCL5.1 134.3,37.3 131.76,39.52 131.76,46.19 130.49,47.46 122.55,47.46
  Bottom 1.93: IC10.14 122.55,38.57 122.55,47.46 122.55,53.81 IC8.14
+15VD  (via drill 0.6)  (3 unrouted)
  Top 0.305: v96.2,44.6 96.2,54.76 101.59,59.84 v106.04,59.84
  Top 1.016: J3.4 137.79,80.48 136.52,81.75 126.04,81.75
  Bottom 0.305: R33.2 63.5,19.52 64.77,18.25 64.77,13.81 66.03,12.54 73.66,12.54 82.55,21.42 82.55,26.5 89.53,33.49 90.8,33.49 92.7,35.39 95.88,38.89 95.88,43.97 v96.2,44.6 | v106.04,59.84 106.04,65.88 111.12,70.95 111.12,72.54 111.75,73.18 116.2,73.18 117.79,74.77 117.79,77.62 117.47,77.94
  Bottom 0.61: J3.4 137.79,72.86 144.14,66.51 144.14,60.16 146.68,57.62 147.95,57.62 149.22,56.35 J4.6 149.22,53.81
  Bottom 1.676: IC1.OUT 103.5,94.45 106.04,91.91 | 106.04,90.64 C3.+
  pour Bottom: 98.42,71.59 98.42,96.99 126.36,96.99 126.36,71.59
ARGGG\  (via drill 0.6)
  Top 0.305: v95.24,46.19 95.24,51.27 93.34,53.17 IC7.13 IC7.12 | IC14.2 IC14.1 43.81,24.6 | IC14.13 IC14.14 43.81,24.6 | 43.81,24.6 R30.2
  Bottom 0.305: 58.41,22.06 57.15,22.06 54.61,24.6 IC14.14 | 58.41,22.06 R32.2 62.86,22.06 66.03,18.88 66.03,13.81 66.67,13.17 73.02,13.17 81.91,22.06 81.91,27.14 88.89,34.12 90.16,34.12 95.24,39.2 v95.24,46.19 | R41.2 59.69,14.44 58.41,15.71 58.41,22.06
CTSIG1
  Bottom 0.61: J5.1 142.01,23.74 R39.1
CTSIG2
  Bottom 0.61: J5.2 144.34,20.99 R43.1
DRIVE  (via drill 0.6)
  Top 0.305: IC2.2 114.3,91.91 113.02,93.18 113.02,95.08 111.12,96.99 97.78,96.99 96.83,96.04 v96.83,92.55
  Bottom 0.305: IC8.10 109.85,58.25 108.9,59.21 107.31,59.21 106.67,58.57 104.13,58.57 103.5,59.21 103.5,65.88 106.99,69.37 106.99,70.95 106.67,71.27 97.78,71.27 97.15,71.91 97.15,92.55 v96.83,92.55
DRIVE\
  Bottom 0.305: IC8.11 112.39,56.67 113.34,57.62 113.34,60.48 113.66,60.8 113.66,64.29 119.38,70 119.38,78.89 117.79,80.48 IC3.2
FTUN
  Bottom 0.61: LCL4.2 144.14,46.19 145.21,47.26 J4.4 | J4.4 | J4.4
FTUN_F
  Bottom 0.305: LCL4.1 136.52,42.38 135.25,41.11 R18.2
GNDA  (3 unrouted)
  pour Top: 1.9,96.99 1.9,3.01 158.11,3.01 158.11,96.99 147.95,96.99 147.95,91.91 153.03,91.91 153.03,81.75 126.36,81.75 126.36,96.99 22.54,96.99 22.54,79.21 97.15,79.21 97.15,71.59 131.44,71.59 131.44,68.73 93.34,68.73 93.34,76.67 21.58,76.67 21.58,96.99
INT+
  Bottom 0.406: J4.2 | R5.1 140.33,57.8 145.39,52.74 J4.2 | J4.2 146.75,52.8
INT-
  Bottom 0.406: PC1.2 141.6,52.54 144.14,50 J4.3
INTQ  (via drill 0.6)
  Top 0.305: v93.97,47.46 93.97,48.09 v92.07,50 | IC8.2 117.47,58.89 118.74,57.62 v118.74,53.17
  Bottom 0.305: 106.04,48.09 IC10.6 | 106.04,48.09 105.41,48.73 95.24,48.73 v93.97,47.46 | v92.07,50 78.73,50 75.56,53.17 64.13,53.17 62.86,51.91 52.07,51.91 50.16,50 41.91,50 41.27,49.37 38.1,49.37 37.46,48.73 IC9.13 | v118.74,53.17 119.38,53.17 120.64,51.91 120.64,49.37 119.38,48.09 106.04,48.09
INTQ\  (via drill 0.6)
  Top 0.305: v98.1,50.32 v98.1,44.6
  Bottom 0.305: IC10.12 113.66,40.48 112.71,41.43 99.37,41.43 98.1,42.7 v98.1,44.6 | v98.1,50.32 94.29,50.32 93.34,51.27 91.12,51.27 90.48,50.63 79.05,50.63 75.88,53.81 63.5,53.81 62.23,52.54 51.43,52.54 49.53,50.63 37.46,50.63 34.92,48.09 IC9.12
METER+
  Bottom 0.305: LCL2.1 137.79,66.51 140.33,63.97 140.33,62.7 139.06,61.43 130.17,61.43 127.63,58.89 R7.2
N$1
  Bottom 0.305: IC13.7 113.66,27.14 112.39,28.41 C22.2
N$2
  Bottom 0.305: IC10.10 108.58,35.39 106.04,32.85 R26.1
N$3
  Bottom 0.305: Q3.E 100.96,10.63 | 100.96,10.63 Q4.E IC13.9 | 100.96,10.63 IC12.7 100.96,19.52 99.69,20.79 97.15,20.79 92.7,25.23 90.48,25.23 89.53,24.28 R35.1
N$4
  Top 0.305: IC12.3 98.42,23.33 95.88,20.79 IC12.5
  Bottom 0.305: R42.1 IC12.5 95.88,19.52 R36.2
N$5
  Bottom 0.61: R28.2 133.98,19.52 C24.1 130.17,18.25 IC13.16 128.9,15.71 D8.C
N$6
  Bottom 0.305: J4.1 146.27,55.49 142.87,58.89 LCL3.2
N$7
  Bottom 0.305: IC13.6 C22.1
N$8
  Bottom 0.305: IC6.5 60.32,70.64 61.27,71.59 66.99,71.59 68.26,70.32 68.26,69.37 IC6.2
N$9  (via drill 0.6)
  Top 0.305: v126.36,41.74 121.6,41.74 v119.69,43.65 | v100.01,44.6 100.01,50.95 99.05,52.22 v99.05,53.49
  Bottom 0.305: IC6.1 70.16,69.05 70.16,67.78 68.57,66.19 60.32,66.19 57.78,63.65 IC6.9 57.78,59.52 59.05,58.25 74.61,58.25 80.32,52.54 89.53,52.54 90.16,53.17 98.74,53.17 v99.05,53.49 | R23.1 128.58,30.95 126.68,32.85 126.68,41.43 v126.36,41.74 | v119.69,43.65 100.96,43.65 v100.01,44.6
N$10
  Bottom 0.305: R23.2 121.28,30.95 123.82,28.41 IC13.3
N$11
  Bottom 0.305: R46.2 117.47,10.63 116.2,11.9 IC13.11
N$12  (via drill 0.6)
  Top 0.305: v114.93,51.91 123.19,51.91 126.36,55.08 PC1.4
  Bottom 0.305: R10.1 135.25,48.73 133.98,50 133.98,53.81 132.71,55.08 PC1.4 | IC9.5 29.84,56.35 32.38,58.89 43.18,58.89 43.81,58.25 47.62,58.25 50.8,55.08 72.38,55.08 73.02,55.71 74.92,55.71 79.37,51.27 90.16,51.27 90.8,51.91 93.97,51.91 94.61,51.27 114.3,51.27 v114.93,51.91
N$13  (via drill 0.6)
  Top 0.305: v71.75,56.03 73.66,56.67 76.83,59.84 80,59.84 81.27,61.11 81.27,61.43 | IC7.6 81.59,63.97 81.27,63.65 81.27,61.43 | IC7.3 88.89,62.06 88.26,61.43 83.81,61.43 | 81.27,61.43 83.81,61.43 | 83.81,61.43 IC7.5
  Bottom 0.305: IC5.3 40,67.14 43.81,63.34 43.81,59.84 44.45,59.21 47.62,59.21 51.11,55.71 71.43,55.71 v71.75,56.03
N$14
  Bottom 0.305: R46.1 109.85,6.82 107.31,4.28 91.75,4.28 90.48,5.55 90.48,6.82 86.99,10.31 83.18,10.31 80.32,7.46 80.32,5.87 79.69,5.23 41.59,5.23 40.95,5.87 39.05,5.87 37.46,4.28 15.24,4.28 14.28,5.23 14.28,14.76 6.98,22.06 VR5.P_WIPE VR5.P_CCW 5.71,24.92
N$15
  Bottom 0.406: LCL2.2 142.87,75.4 146.48,79.01 J2.4
N$16  (via drill 0.6)
  Top 0.305: IC7.9 81.27,57.94 82.86,59.52 v84.77,59.52
  Bottom 0.305: IC7.8 IC7.9 | v84.77,59.52 86.35,61.11 IC7.4
N$17
  Bottom 0.305: R34.2 89.53,25.87 93.34,25.87 97.15,22.06 100.96,22.06 103.5,24.6 IC12.1 104.77,25.87 107.31,28.41 C20.1 108.58,32.22 109.85,33.49 113.02,33.49 114.3,34.76 114.3,35.39 113.66,36.03 112.39,36.03 111.12,37.3 IC10.11
N$18
  Bottom 0.305: IC6.11 62.86,59.21 63.18,58.89 81.27,58.89 IC7.10
N$19
  Top 0.305: C20.2 102.23,30.95 100.96,29.68 | 100.96,29.68 IC12.2 | R26.2 100.96,29.68
  Bottom 0.305: R26.2 95.24,29.04 88.89,29.04 85.08,25.23 85.08,19.52 72.07,6.5 42.54,6.5 41.91,7.14 37.78,7.14 36.51,5.87 16.82,5.87 16.19,6.5 16.19,17.93 5.71,28.41 VR4.P_CW
N$20
  Bottom 0.61: C25.2 135.25,10.63 123.82,10.63 | D9.C 123.82,10.63 | 123.82,10.63 D8.A 122.55,13.17 123.82,14.44 IC13.14
N$21
  Bottom 1.778: B1.+ 48.89,83.66 48.26,83.02 F1.1 40.95,83.02
N$22
  Bottom 0.305: R29.2 120.01,28.41 121.28,27.14 IC13.4
N$23  (via drill 0.6)
  Top 0.305: v75.24,64.92 66.99,64.92 65.08,66.83 65.08,68.73 IC6.3 | v125.09,40.16 124.45,40.79 119.06,40.79 v118.1,41.74 | v99.05,46.19 99.05,50.95 97.78,52.54 97.78,54.13 v99.69,55.08 | IC7.1 v93.97,58.57
  Bottom 0.305: IC7.1 IC7.2 91.44,65.56 90.16,66.83 78.1,66.83 76.19,64.92 v75.24,64.92 | R29.1 128.9,28.73 125.09,32.54 v125.09,40.16 | v118.1,41.74 118.1,42.06 117.47,42.7 100.32,42.7 99.05,43.97 v99.05,46.19 | v99.69,55.08 97.78,55.08 94.61,58.57 v93.97,58.57
N$24
  Bottom 0.305: R45.2 R41.1 | R45.2 R48.2 | IC14.9 R45.2
N$25
  Bottom 1.778: J1.1 31.74,84.29 33.65,86.19 33.65,87.47 35.55,89.37 B1.AC1
N$26
  Bottom 0.305: R5.2 133.98,58.89 135.25,57.62 135.25,51.27 136.52,50 PC1.1
N$27
  Top 0.305: R14.2 65.4,32.22 R22.1
  Bottom 0.305: R14.2 IC11.6
N$28
  Bottom 0.305: IC11.1 IC11.2 R14.1 R13.2
N$29
  Bottom 0.61: R39.2 140.33,13.17 C25.1
N$30
  Bottom 0.61: LCL5.2 142.87,37.3 146.68,41.11 J4.5 146.68,44.92
N$31  (via drill 0.6)
  Top 0.305: v114.61,58.57 108.58,58.57 v107.94,57.94 | v80.64,74.77 80,75.08 38.41,75.08 C13.1
  Bottom 0.305: IC8.1 120.01,60.48 118.74,59.21 115.25,59.21 v114.61,58.57 | v107.94,57.94 103.82,57.94 102.86,57.3 98.74,57.3 96.2,60.16 96.2,65.24 93.02,68.41 93.02,72.86 91.12,74.77 v80.64,74.77 | VR1.P_WIPE VR1.P_CW 5.71,77.62 3.8,79.53 3.8,81.75 5.08,83.02 18.09,83.02 22.22,78.89 22.22,71.59 26.35,67.46 27.3,67.46 28.25,68.41 28.25,71.59 29.52,72.86 C13.1 36.51,73.18
N$32  (via drill 0.6)
  Top 0.305: v45.08,73.5 46.03,74.45 77.78,74.45 v78.73,73.5
  Bottom 0.305: IC8.13 117.47,54.13 116.2,52.86 114.93,52.86 114.61,53.17 107.63,53.17 107.31,53.49 IC8.9 107.31,56.03 106.36,56.98 103.82,56.98 103.18,56.67 98.42,56.67 95.56,59.84 95.56,64.92 92.39,68.1 92.39,71.91 90.8,73.5 v78.73,73.5 | IC5.1 v45.08,73.5
N$33  (via drill 0.6)
  Top 0.305: IC9.11 32.38,48.09 34.92,50.63 IC9.3 | v67.94,56.67 IC6.13 | v49.84,52.86 v53.65,56.67
  Bottom 0.305: IC8.8 103.5,52.22 94.93,52.22 94.61,52.54 90.48,52.54 89.85,51.91 79.69,51.91 74.61,56.98 69.21,56.98 v67.94,56.67 v53.65,56.67 | IC9.3 34.92,56.03 35.87,56.98 42.86,56.98 43.18,56.67 46.03,56.67 v49.84,52.86
N$34  (via drill 0.6)
  Top 0.305: v102.86,55.71 v103.82,50.32 | v112.71,50.32 112.71,52.22 114.93,54.45 IC8.12
  Bottom 0.305: IC6.12 65.4,60.16 66.03,59.52 82.23,59.52 83.5,58.25 85.72,58.25 87.31,59.84 94.61,59.84 98.1,55.71 98.74,55.71 99.05,56.03 101.28,56.03 101.59,55.71 v102.86,55.71 | v103.82,50.32 v112.71,50.32
N$35  (via drill 0.6)
  Top 0.305: IC8.4 112.39,63.65 110.8,65.24 101.28,65.24 100.64,64.92 v97.47,64.92
  Bottom 0.305: v97.47,64.92 97.47,65.24 93.97,68.73 93.97,73.81 92.07,75.72 80.96,75.72 78.42,78.26 40.64,78.26 38.41,76.03 38.41,73.18 36.51,71.27 33.97,71.27 32.38,69.69 32.38,69.37 32.06,69.05 IC5.6
N$36
  Top 0.305: IC8.6 107.31,60.8 107.94,60.16 109.85,60.16 | 109.85,60.16 114.3,60.16 114.93,60.8 IC8.3 | 109.85,60.16 IC8.5
N$37
  Bottom 0.305: R43.2 142.87,6.82 C26.1
N$38
  Bottom 0.305: R32.1 R33.1 R38.2 IC14.11
N$39
  Top 0.305: IC9.1 40,56.35 37.46,58.89 IC5.11
  Bottom 0.305: IC9.9 27.3,50 29.84,52.54 39.72,52.5 40,52.82 IC9.1
N$40  (via drill 0.6)
  Top 0.305: IC5.8 29.84,58.25 32.38,55.71 IC9.4 | v73.97,54.76 74.61,53.81 v82.23,53.81
  Bottom 0.305: v73.97,54.76 73.66,54.45 59.37,54.45 59.05,54.13 50.16,54.13 46.98,57.3 43.49,57.3 42.86,57.94 33.97,57.94 32.38,56.35 IC9.4 | v82.23,53.81 85.72,53.81 86.35,54.45 IC7.11
N$41
  Bottom 0.305: R25.2 R22.2 IC11.7
N$42
  Bottom 0.305: Q4.B Q3.B 97.47,9.36 96.2,10.63 96.2,12.22 | 96.2,12.22 98.42,14.44 IC12.6 | R34.1 R35.2 90.8,14.44 93.34,14.44 94.61,13.17 95.24,13.17 96.2,12.22
N$43
  Bottom 0.305: LED1.A 8.25,89.37 9.52,88.1 R4.2
N$44
  Bottom 0.305: IC5.13 42.54,62.7 40.64,64.61 26.03,64.61 20.31,70.32 20.31,74.77 R4.1
N$45  (via drill 0.6)
  Top 0.305: R44.2 R40.2 | IC11.3 70.48,42.38 69.21,41.11 69.21,36.66 v69.84,36.03 | v44.45,19.52 41.91,16.98 IC14.4 | IC14.7 v40,4.6
  Bottom 0.305: C26.2 133.98,3.01 88.89,3.01 87.31,4.6 87.31,8.41 86.04,9.68 83.81,9.68 81.27,7.14 81.27,5.55 80.32,4.6 v40,4.6 | R40.2 31.11,14.44 34.92,18.25 D7.A | D7.A D6.C | D7.A 36.19,19.52 38.73,16.98 IC14.4 41.27,16.98 42.54,15.71 42.54,10 41.91,9.36 IC14.7 | v69.84,36.03 63.5,36.03 60.96,33.49 60.96,31.58 60.32,30.95 57.78,30.95 57.15,30.31 53.97,30.31 51.43,27.77 48.26,27.77 43.81,23.33 43.81,20.15 v44.45,19.52
N$46
  Top 0.305: R13.1 64.13,34.76 60.96,37.94 Q1.2
N$47
  Bottom 0.305: R20.2 111.12,34.76 109.85,36.03 109.85,39.84 109.21,40.79 106.99,40.79 106.04,39.84 IC10.9 R19.2
N$48
  Bottom 0.305: IC13.2 126.36,28.41 122.55,32.22 R20.1
N$49
  Bottom 0.305: R19.1 95.88,32.85 93.34,30.31 88.89,30.31 84.45,25.87 84.45,20.15 71.75,7.46 43.49,7.46 42.86,8.09 37.46,8.09 35.87,6.5 18.41,6.5 17.46,7.46 17.46,19.2 8.57,28.09 8.57,38.89 3.8,43.65 3.8,49.37 4.44,50 VR3.P_WIPE 6.03,50
N$50
  Bottom 0.305: IC10.8 103.5,36.03 98.42,30.95 98.42,30 96.52,28.09 89.21,28.09 85.72,24.6 85.72,18.88 72.7,5.87 42.22,5.87 41.59,6.5 38.41,6.5 37.14,5.23 16.19,5.23 15.55,5.87 15.55,17.61 4.12,29.04 4.12,36.03 | 4.12,36.03 4.12,37.94 4.76,38.57 VR4.P_CCW 6.03,38.25 | 4.12,36.03 VR4.P_WIPE
N$51
  Bottom 0.305: R50.1 95.88,6.82 103.5,6.82 Q4.C
N$52
  Bottom 0.305: R50.2 84.45,4.6 82.86,3.01 12.7,3.01 10.79,4.92 10.79,11.9 9.52,13.17 LED3.A
N$53
  Bottom 0.305: R49.2 83.81,8.09 82.55,6.82 82.55,4.6 81.59,3.64 13.97,3.64 12.06,5.55 LED4.K
N$54
  Bottom 0.305: R49.1 Q3.C
N$55
  Bottom 0.305: R44.1 R47.2 | R44.1 IC14.6 | R44.1 29.2,11.9 27.93,10.63 20,10.63 18.73,11.9 18.73,21.42 10.47,29.68 10.47,50.63 3.49,57.62 3.49,65.56 4.44,66.51 5.39,66.51 5.71,66.19 VR2.P_CCW
N$56
  Bottom 0.305: IC14.5 R40.1 R37.1 35.55,16.98 31.74,13.17 20.95,13.17 19.68,14.44 19.68,21.74 11.43,30 11.43,50.95 5.71,56.67 VR2.P_CW VR2.P_WIPE
N$57
  Top 0.305: R25.1 58.41,29.68 57.15,30.95 Q2.2
N$58
  Bottom 0.305: R9.1 61.59,41.11 Q1.3 58.41,41.11 57.78,41.74 46.98,41.74 D2.C
N$59
  Bottom 0.305: R12.1 Q2.3 50.16,36.03 49.53,36.66 46.98,36.66 D3.C
N$60
  Bottom 0.305: D2.A R16.2 D3.A
N$61
  Bottom 0.305: R16.1 45.72,37.3 48.26,39.84 C18.1 49.53,39.84 50.8,38.57 R11.1 53.97,39.84 55.88,39.84 56.51,39.2 56.51,37.94 58.41,36.66 60.32,36.66 62.23,38.57 74.92,38.57 76.19,37.3 IC11.10
N$62
  Bottom 1.778: J1.3 38.73,94.45 41.27,91.91 46.35,91.91 B1.AC2
N$63
  Bottom 0.305: D5.C 74.29,30.31 76.19,32.22 IC11.8 81.27,32.22 R17.1
N$64
  Bottom 0.305: D4.C D5.A
N$65
  Bottom 0.305: IC11.9 76.83,34.76 71.75,29.68 D4.A 69.84,27.14 R31.1
N$66
  Bottom 0.305: R15.1 85.08,38.57 R17.2 82.55,41.74 IC11.13 78.73,44.92 77.46,46.19 77.46,49.37 R6.1
N$67
  Bottom 0.305: ZD1.C IC11.14
N$68
  Bottom 0.305: R15.2 85.08,43.65 86.35,44.92 ZD1.A R8.2 93.97,49.37 105.72,49.37 106.36,48.73 116.2,48.73 R7.1
N$69
  Bottom 0.305: R3.2 20,90.96 18.41,89.37 LED2.A
N$70
  Bottom 0.305: IC5.2 42.54,69.69 41.27,70.95 39.37,70.95 38.73,70.32 38.73,66.83 38.1,66.19 26.03,66.19 21.27,70.95 21.27,77.62 17.46,81.43 6.66,81.43 VR1.P_CCW
N$71
  Bottom 0.61: R27.1 135.25,25.87 132.71,25.87 131.44,24.6 131.44,22.06 130.17,20.79 120.01,20.79 118.74,19.52 IC13.12
N$72
  Bottom 0.305: R27.2 R18.1 132.71,33.49 131.44,34.76 C19.1
N$73  (2 unrouted)
  Bottom 1.676: IC2.7 128.9,91.91 C1.1 | IC2.6 131.44,89.37 C5.1
  pour Bottom: 127.63,88.1 127.63,96.99 142.87,96.99 142.87,88.1
N$74
  Bottom 1.778: F1.2 57.46,83.02 55.24,85.24 LCL1.1
N$75  (3 unrouted)
OUT  (2 unrouted)
  Bottom 1.676: 127.95,80.48 IC3.7 | 127.95,80.48 139.06,84.29 146.68,84.29 J2.2 | IC3.6 127.95,77.94 127.95,80.48
  pour Bottom: 127.63,86.83 144.14,86.83 144.14,89.37 147.95,89.37 147.95,83.02 145.41,83.02 131.44,74.13 127.63,74.13
OUT\
  pour Top: 127.63,96.99 142.87,96.99 142.87,90.64 151.76,90.64 151.76,83.02 127.63,83.02
SYNC  (via drill 0.6)
  Top 0.305: J3.1 130.17,72.86 128.9,71.59 98.42,71.59 97.15,72.86 97.15,77.94 95.88,79.21 v66.67,79.21
  Bottom 0.305: v66.67,79.21 D1.A
  Bottom 1.778: LCL1.2 R1.2 D1.A
TRIAC
  Bottom 0.406: J3.6 J2.3
UNREG  (via drill 0.6)  (1 unrouted)
  Top 0.305: v97.15,46.19 96.83,46.51 96.83,54.45 101.28,58.57 v102.23,58.57
  Top 1.676: IC4.IN v105.41,70.32 97.15,70.32 95.88,71.59 v95.88,75.4
  Bottom 0.305: R45.1 74.29,11.9 83.18,20.79 83.18,25.87 89.53,32.22 90.8,32.22 97.15,38.57 v97.15,46.19 | v102.23,58.57 102.23,60.8 102.86,61.43 102.86,66.51 105.41,69.05 v105.41,70.32
  Bottom 1.676: v95.88,75.4 95.88,80.48 88.26,91.91 | 88.26,91.91 IC1.IN | 88.26,91.91 77.46,91.91 C7.+
  Bottom 1.778: D1.C 70.48,91.91 77.46,91.91
VCC/2
  Top 0.305: IC11.5 74.29,34.76 76.19,34.76 78.1,42.38 IC11.12
  Bottom 0.305: 46.35,9.36 44.45,11.27 44.45,14.44 41.91,21.42 41.91,28.41 R24.1 42.54,30.95 | 42.54,30.95 R21.2 | 42.54,30.95 C21.1 46.35,32.22 51.43,32.22 52.07,31.58 56.51,31.58 62.23,37.3 IC11.5
VOLT_F
  Bottom 0.305: LCL3.1 137.47,63.97 135.88,65.56 135.88,73.81 135.25,74.45 J3.3

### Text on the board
tPlace: LIMIT/ | POWER | FAULT | GATE DRIVE | DIMMER SW. | 15V AC IN | S J C | DEAD- | TIME | LIMIT | CURRENT | DRIVER | INTERRUPTER | PHASE | TARGET | LOOP | GAIN | *SSTC | PHASE LOCKED LOOP | TUNING | File name | MADE IN SCOTLAND BY STEVE CONNER 2004-2005 | TUNING AID | MAY CONTAIN TRACES OF NUT | LOW | HIGH | CURRENT SENSOR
